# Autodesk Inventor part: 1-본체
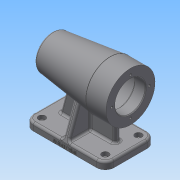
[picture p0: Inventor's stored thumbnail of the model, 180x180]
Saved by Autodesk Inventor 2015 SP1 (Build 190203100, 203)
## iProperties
Created: 2018-09
Part Number: 1-본체
Material: Generic
Document SubType Name: Modeling
Designer: Administrator
Density: 1 g/cm^3
Appearance: Default
Author: Administrator
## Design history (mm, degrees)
sketch "스케치1"
  geometry: L1 (-56, 35)-(56, 35); L2 (56, 35)-(56, -35); L3 (56, -35)-(-56, -35); L4 (-56, -35)-(-56, 35); L5 (-56, 35)-(56, -35); L6 (56, 35)-(-56, -35); 1 further point
  constraints: 12 end point, 2 midpoint, 2 parallel, 1 horizontal, 1 perpendicular
  dimensions: "d0" = 112 distance of L1.start L1.end; "d1" = 70 distance of L1.end L2.end
extrude "돌출1" new body sketch "스케치1" distance "d2" = 10; taper "d3" = 0 deg
fillet "모깎기1" dims "d4" = 12
hole "구멍1" diameter "d7" = 5.5; stored, may be unused: countersink angle "d11" = 90 deg, drill point angle "d13" = 0 deg; dims "d5" = 10, "d6" = 10, "d8" = 6, "d9" = 9.5, "d10" = 5.4, "d12" = 8
hole "구멍2" diameter "d16" = 5.5; stored, may be unused: countersink angle "d20" = 90 deg, drill point angle "d22" = 0 deg; dims "d14" = 10, "d15" = 10, "d17" = 6, "d18" = 9.5, "d19" = 5.4, "d21" = 8
hole "구멍3" diameter "d25" = 5.5; stored, may be unused: countersink angle "d29" = 90 deg, drill point angle "d31" = 0 deg; dims "d23" = 10, "d24" = 10, "d26" = 6, "d27" = 9.5, "d28" = 5.4, "d30" = 8
hole "구멍4" diameter "d34" = 5.5; stored, may be unused: countersink angle "d38" = 90 deg, drill point angle "d40" = 0 deg; dims "d32" = 10, "d33" = 10, "d35" = 6, "d36" = 9.5, "d37" = 5.4, "d39" = 8
node "작업 평면1"
sketch "스케치2"
  geometry: L1 (-12, 74)-(100, 74); L2 (0, 0)-(88, 0) reference; L3 (0, 0)-(-12, 0) reference; L4 (100, 0)-(88, 0) reference; L5 (88, 0)-(88, 10) reference; L6 (0, 0)-(88, 0) reference; L7 (0, 10)-(0, 0) reference; L8 (88, 10)-(0, 10) reference; L9 (100, 74)-(100, 108); L10 (100, 108)-(72, 108); L11 (72, 108)-(-8.27, 98.144); L12 (100, 95)-(85, 95); L13 (85, 95)-(85, 98); L14 (85, 98)-(31, 98); L15 (31, 98)-(31, 95); L16 (31, 95)-(19, 95); L17 (19, 95)-(19, 91.5); L18 (19, 91.5)-(1, 91.5); L19 (1, 91.5)-(1, 90); L20 (1, 90)-(-3, 90); L21 (-3, 90)-(-3, 84.5); L22 (-3, 84.5)-(-6, 84.5); L23 (-6, 84.5)-(-6, 74); A1 r 80 centre (68, 74) between (-8.27, 98.144) and (-12, 74); 3 further points
  constraints: 32 end point, 11 perpendicular, 5 point on line, 2 horizontal, 2 midpoint, 2 point on circle, 1 centre point, 1 vertical, 1 vertical alignment
  dimensions: "d41" = 74 distance between parallel lines of L2 L1; "d42" = 28 distance of L9.end L10.end; "d43" = 68 diameter of L10 L1; "d44" = 112 distance of L1.start L1.end; "d45" = 7 deg angle of L10 L11; "d47" = 48 diameter of L14 L1; "d48" = 42 diameter of L16 L1; "d49" = 35 diameter of L18 L1; "d50" = 32 diameter of L20 L1; "d51" = 21 diameter of L22 L1; "d52" = 54 distance of L13.end L14.end; "d53" = 15 distance of L12.start L12.end; "d54" = 12 distance of L15.end L16.end; "d55" = 18 distance of L17.end L18.end; "d56" = 4 distance of L19.end L20.end; "d57" = 3 distance of L21.end L22.end; "d95" = 80 radius of A1
  node "투영된 루프1"
revolve "회전1" stored, may be unused: angle "d46" = 90 deg
sketch "스케치3"
  geometry: L1 (88, 0)-(88, 10) reference; L2 (0, 0)-(88, 0) reference; L3 (0, 10)-(0, 0) reference; L4 (88, 10)-(0, 10) reference; L5 (82, 10)-(82, 92.105); L6 (82, 92.105)-(28, 92.105); L7 (100, 10)-(100, 0) reference; L8 (-12, 0)-(-12, 10) reference; L9 (-12, 10)-(0, 10) reference; L10 (28, 92.105)-(6, 10); L11 (0, 10)-(88, 10) reference; 1 further point
  constraints: 6 end point, 2 perpendicular, 2 point on line
  dimensions: "d58" = 18 distance between parallel lines of L7 L5; "d60" = 54 distance of L5.end L6.end; "d108" = 105 deg angle of L10 L9; "d109" = 18 distance from line of L10.end L8
extrude "돌출2" join sketch "스케치3" stored distance "d61" = 8; taper "d62" = 0 deg
node "작업 평면2"
fillet "모깎기6" dims "d85" = 3
sketch "스케치4"
  geometry: L1 (7, 46)-(0, 46) reference; L2 (0, 46)-(0, 58) reference; L3 (0, 58)-(7, 58) reference; L4 (10, 58)-(10, 46) reference; L5 (10, -12)-(0, -12) reference; L6 (7, 46)-(7, 58) reference; L7 (10, 55)-(10, 46) reference; L8 (10, 46)-(10, 0) reference; L9 (10, 0)-(10, -9) reference; L10 (8.026, -11.819)-(69.675, 10.619); L11 (69.675, 10.619)-(69.675, 35.381); L12 (69.675, 35.381)-(8.026, 57.819); A1 r 3 centre (7, 55) between (10, 55) and (7, 58) reference; A2 r 3 centre (7, -9) between (7, -12) and (10, -9) reference; 1 further point
  constraints: 6 end point, 2 point on circle, 2 tangent, 1 vertical
  dimensions: "d86" = 20 deg angle of L5 L10; "d87" = 20 deg angle of L12 L3; "d88" = 24.76131 distance of L10.end L11.end
extrude "돌출3" join sketch "스케치4" stored distance "d66" = 8; taper "d67" = 0 deg
revolve "회전2" stored, may be unused: angle "d68" = 90 deg
sketch "스케치6"
  geometry: L1 (100, 0)-(100, 10) reference; L2 (88, 0)-(0, 0) reference; 2 further points
  constraints: 1 other
  dimensions: "d77" = 56 distance from line of L1 point (44, 3); "d78" = 3 distance from line of point (44, 3) L2
feature "엠보싱1" sketch "스케치6" dims "d0" = 112, "d1" = 70, "d23" = 10, "d24" = 10, "d79" = 0.5, "d80" = 0
fillet "모깎기4" dims "d83" = 3
fillet "모깎기7" dims "d89" = 3
fillet "모깎기13" dims "d110" = 3
fillet "모깎기14" dims "d111" = 3
chamfer "모따기1" distance "d90" = 1; stored, may be unused: second distance "d91" = 2, angle "d92" = 45 deg
fillet "모깎기10" dims "d96" = 3
fillet "모깎기11" dims "d97" = 3, "d98" = 0.3
sketch "스케치7"
  geometry: C1 r 34 at (0, 0) reference; C2 r 22 at (0, 0) reference; A1 r 26 centre (0, 0) between (-26, 0) and (0, -26); 3 further points
  constraints: 4 point on circle, 2 horizontal alignment, 2 vertical alignment, 1 centre point, 1 coincident
  dimensions: "d99" = 52 diameter of A1
hole "구멍6" sketch "스케치7" at (-26, 0), (0, -26), (26, 0), (0, 26) diameter "d100" = 3.242; stored, may be unused: countersink angle "d104" = 90 deg, drill point angle "d106" = 118 deg; dims "d101" = 8, "d102" = 9.5, "d103" = 5.4, "d105" = 11
fillet "모깎기12" dims "d107" = 3
node "솔리드1"
node "투영된 루프2"
node "투영된 루프3"
node "투영된 루프5"
